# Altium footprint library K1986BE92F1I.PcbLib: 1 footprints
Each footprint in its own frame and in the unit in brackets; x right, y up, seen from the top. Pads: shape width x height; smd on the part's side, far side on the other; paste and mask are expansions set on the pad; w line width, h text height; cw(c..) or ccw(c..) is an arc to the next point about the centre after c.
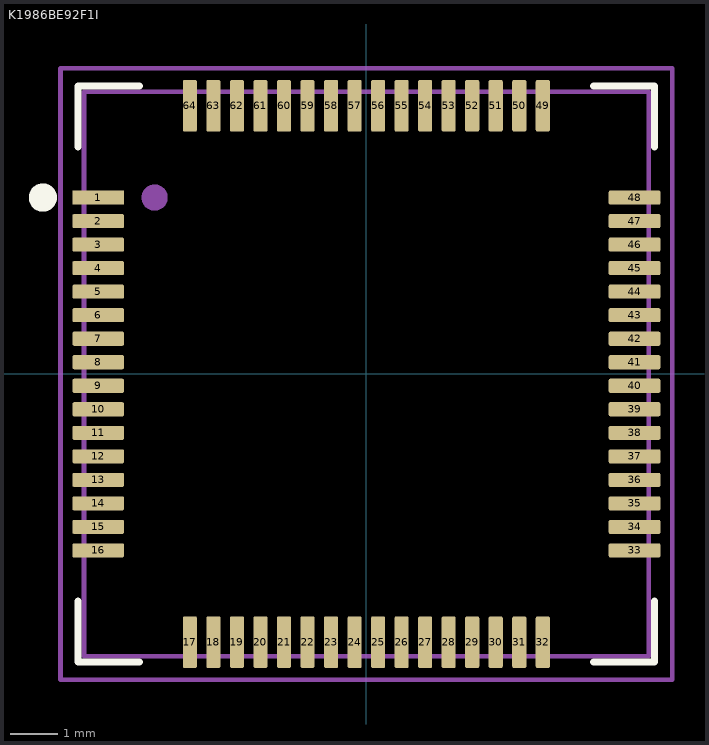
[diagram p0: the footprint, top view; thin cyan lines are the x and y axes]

## K1986BE92F1I [mm] "QFN64 12x12x1,6(0,5)"
height 1.6
pads (64):
  rect 1.1x0.3 smd mask+0.05: 1(-5.7,3.75)
  rrect25% 1.1x0.3 smd mask+0.05: 2(-5.7,3.25) 3(-5.7,2.75) 4(-5.7,2.25) 5(-5.7,1.75) 6(-5.7,1.25) 7(-5.7,0.75) 8(-5.7,0.25) 9(-5.7,-0.25) 10(-5.7,-0.75) 11(-5.7,-1.25) 12(-5.7,-1.75) 13(-5.7,-2.25) 14(-5.7,-2.75) 15(-5.7,-3.25) 16(-5.7,-3.75) 33(5.7,-3.75) 34(5.7,-3.25) 35(5.7,-2.75) 36(5.7,-2.25) 37(5.7,-1.75) 38(5.7,-1.25) 39(5.7,-0.75) 40(5.7,-0.25) 41(5.7,0.25) 42(5.7,0.75) 43(5.7,1.25) 44(5.7,1.75) 45(5.7,2.25) 46(5.7,2.75) 47(5.7,3.25) 48(5.7,3.75)
  rrect25% 0.3x1.1 smd mask+0.05: 17(-3.75,-5.7) 18(-3.25,-5.7) 19(-2.75,-5.7) 20(-2.25,-5.7) 21(-1.75,-5.7) 22(-1.25,-5.7) 23(-0.75,-5.7) 24(-0.25,-5.7) 25(0.25,-5.7) 26(0.75,-5.7) 27(1.25,-5.7) 28(1.75,-5.7) 29(2.25,-5.7) 30(2.75,-5.7) 31(3.25,-5.7) 32(3.75,-5.7) 49(3.75,5.7) 50(3.25,5.7) 51(2.75,5.7) 52(2.25,5.7) 53(1.75,5.7) 54(1.25,5.7) 55(0.75,5.7) 56(0.25,5.7) 57(-0.25,5.7) 58(-0.75,5.7) 59(-1.25,5.7) 60(-1.75,5.7) 61(-2.25,5.7) 62(-2.75,5.7) 63(-3.25,5.7) 64(-3.75,5.7)
Top Overlay:
  circle w0.3: c-6.875,3.75 r0.15
  lines w0.15: -6.125,-4.825 -6.125,-6.125 -4.825,-6.125 ; -6.125,4.825 -6.125,6.125 -4.825,6.125 ; 4.825,-6.125 6.125,-6.125 6.125,-4.825 ; 4.825,6.125 6.125,6.125 6.125,4.825
Top Assembly:
  circle w0.3: c-4.5,3.75 r0.127
  lines w0.1: -6,-6 -6,6 6,6 6,-6 -6,-6
Top Courtyard:
  lines w0.1: -6.5,-6.5 6.5,-6.5 6.5,6.5 -6.5,6.5 -6.5,-6.5
3D body "Корпус QFN64 12х12(0.5).STEP": height 1.6, standoff 0, extent -6,-6 6,6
